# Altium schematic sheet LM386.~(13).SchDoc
size A4
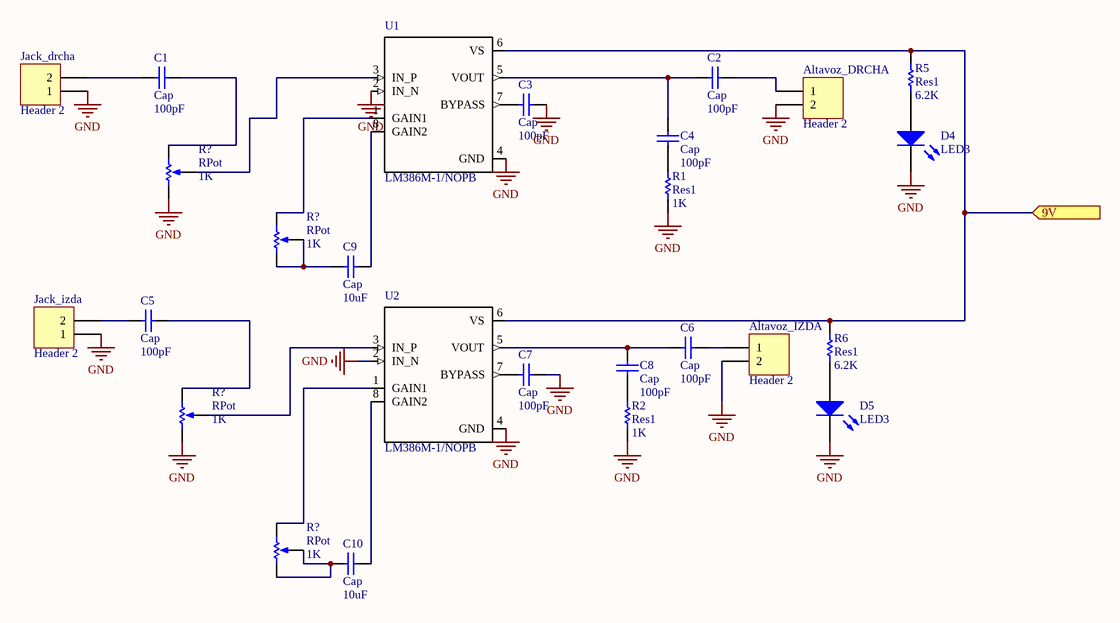
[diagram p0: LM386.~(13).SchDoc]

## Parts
(Parts that share a designator on the sheet are numbered #1, #2 ... from top to bottom, then left to right.)
Altavoz_DRCHA  Header 2  [HDR1X2]
Altavoz_IZDA  Header 2  [HDR1X2]
C1  Cap  value 100pF  [RAD-0.3]
C2  Cap  value 100pF  [RAD-0.3]
C3  Cap  value 100pF  [RAD-0.3]
C4  Cap  value 100pF  [RAD-0.3]
C5  Cap  value 100pF  [RAD-0.3]
C6  Cap  value 100pF  [RAD-0.3]
C7  Cap  value 100pF  [RAD-0.3]
C8  Cap  value 100pF  [RAD-0.3]
C9  Cap  value 10uF  [RAD-0.3]
C10  Cap  value 10uF  [RAD-0.3]
D4  LED3  [3.5X2.8X1.9]
D5  LED3  [3.5X2.8X1.9]
Jack_drcha  Header 2  [HDR1X2]
Jack_izda  Header 2  [HDR1X2]
R1  Res1  value 1K  [AXIAL-0.3]
R2  Res1  value 1K  [AXIAL-0.3]
R5  Res1  value 6.2K  [AXIAL-0.3]
R6  Res1  value 6.2K  [AXIAL-0.3]
R?#1  RPot  value 1K  [VR5]
R?#2  RPot  value 1K  [VR5]
R?#3  RPot  value 1K  [VR5]
R?#4  RPot  value 1K  [VR5]
U1  LM386M-1/NOPB  [SOIC127P600X175-8N]
U2  LM386M-1/NOPB  [SOIC127P600X175-8N]

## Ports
9V (in)

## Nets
GND: Altavoz_DRCHA.2 Altavoz_IZDA.2 C3.1 C7.2 D4.2(K) D5.2(K) Jack_drcha.1 Jack_izda.1 R1.1 R2.1 R?#1.1(TOP) R?#3.1(TOP) U1.2(IN_N) U1.4(GND) U2.2(IN_N) U2.4(GND)
9V: R5.1 R6.1 U1.6(VS) U2.6(VS) ; port 9V
NetAltavoz_DRCHA_1: Altavoz_DRCHA.1 C2.2
NetAltavoz_IZDA_1: Altavoz_IZDA.1 C6.2
NetC1_1: C1.1 R?#1.2(BOT)
NetC1_2: C1.2 Jack_drcha.2
NetC2_1: C2.1 C4.2 U1.5(VOUT)
NetC3_2: C3.2 U1.7(BYPASS)
NetC4_1: C4.1 R1.2
NetC5_1: C5.1 R?#3.2(BOT)
NetC5_2: C5.2 Jack_izda.2
NetC6_1: C6.1 C8.2 U2.5(VOUT)
NetC7_1: C7.1 U2.7(BYPASS)
NetC8_1: C8.1 R2.2
NetC9_1: C9.1 U1.8(GAIN2)
NetC9_2: C9.2 R?#2.1(TOP) R?#2.3(TAP)
NetC10_1: C10.1 U2.8(GAIN2)
NetC10_2: C10.2 R?#4.1(TOP) R?#4.3(TAP)
NetD4_1: D4.1(A) R5.2
NetD5_1: D5.1(A) R6.2
NetR?#1_3: R?#1.3(TAP) U1.3(IN_P)
NetR?#2_2: R?#2.2(BOT) U1.1(GAIN1)
NetR?#3_3: R?#3.3(TAP) U2.3(IN_P)
NetR?#4_2: R?#4.2(BOT) U2.1(GAIN1)

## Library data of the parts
Altavoz_DRCHA Altavoz_IZDA Jack_drcha Jack_izda = Header 2: Header, 2-Pin
C1-C10 = Cap: Capacitor
D4 D5 = LED3: Typical BLUE SiC LED
R1 R2 R5 R6 = Res1: Resistor
R?#1-R?#4 = RPot: Potentiometer; Sim Note: Enter the Resistance value and the set point into parameter fields.; Set Position: 0.5
U1 U2 = LM386M-1/NOPB: Wide Input Voltage Low Power Audio Amplifier with Internal Gain 8-SOIC 0 to 70; MF: Texas Instruments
